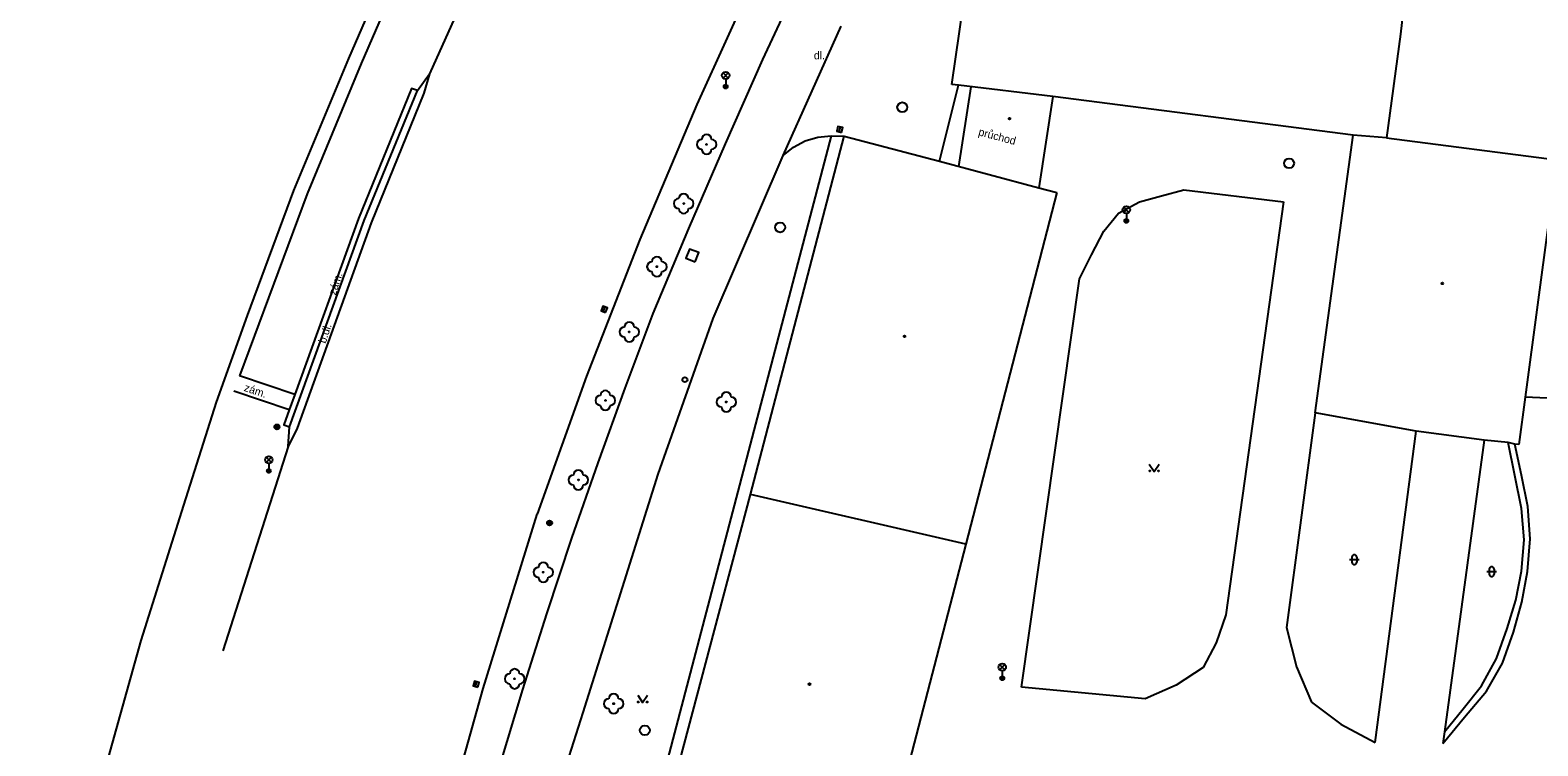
# Model space of a CAD drawing. Extents: x -599770 to -598493, y -1162076 to -1159209.
# Drawn here: x -599183.4 to -599106.9, y -1159771.9 to -1159735.7 of the extents above; entities that cross this region are included whole.
import ezdxf

# ---------------------------------------------------------------- set-up
doc = ezdxf.new("R2010")
doc.units = 0
doc.layers.add('Podklad', color=7, linetype='Continuous')

msp = doc.modelspace()

# ---------------------------------------------------------------- linework, layer by layer
at = {"layer": 'Podklad'}
for p, q in [((-599148.222, -1159738.09), (-599147.957, -1159737.825)), ((-599148.222, -1159737.825), (-599147.957, -1159738.09)), ((-599148.09, -1159738.145), (-599148.09, -1159738.52)), ((-599142.342, -1159740.811), (-599142.278, -1159740.569)), ((-599127.913, -1159744.9), (-599127.648, -1159744.635)), ((-599127.913, -1159744.635), (-599127.648, -1159744.9)), ((-599127.78, -1159744.955), (-599127.78, -1159745.33)), ((-599154.293, -1159749.927), (-599154.207, -1159749.693)), ((-599171.383, -1159757.57), (-599171.118, -1159757.305)), ((-599171.383, -1159757.305), (-599171.118, -1159757.57)), ((-599171.25, -1159757.625), (-599171.25, -1159758)), ((-599116.473, -1159762.498), (-599115.973, -1159762.498)), ((-599116.348, -1159762.373), (-599116.348, -1159762.623)), ((-599116.098, -1159762.373), (-599116.098, -1159762.623)), ((-599109.513, -1159763.108), (-599109.013, -1159763.108)), ((-599109.388, -1159762.983), (-599109.388, -1159763.233)), ((-599109.138, -1159762.983), (-599109.138, -1159763.233)), ((-599134.203, -1159768.08), (-599133.938, -1159767.815)), ((-599134.203, -1159767.815), (-599133.938, -1159768.08)), ((-599160.773, -1159768.931), (-599160.707, -1159768.689)), ((-599134.07, -1159768.135), (-599134.07, -1159768.51))]:
    msp.add_line(p, q, dxfattribs=at)
for points in [[(-599153.26, -1159707.54), (-599161.09, -1159723.46), (-599163.45, -1159728.54), (-599165.36, -1159732.81), (-599167.21, -1159737.09), (-599170, -1159743.79)], [(-599152.46, -1159707.57), (-599154.76, -1159712.01), (-599158.88, -1159720.38), (-599160.49, -1159723.74), (-599162.81, -1159728.83), (-599164.72, -1159733.09), (-599166.57, -1159737.36), (-599169.31, -1159743.95)], [(-599136.92, -1159717.88), (-599138.17, -1159720.27), (-599140.25, -1159724.46), (-599142.28, -1159728.67), (-599143.65, -1159731.64), (-599146.22, -1159737.15), (-599148.12, -1159741.43), (-599149.97, -1159745.72), (-599151.78, -1159750.03)], [(-599157.51, -1159725.43), (-599163.1, -1159737.88)], [(-599146.48, -1159732.66), (-599149.55, -1159739.43), (-599152.44, -1159746.27), (-599155.14, -1159753.2), (-599157.65, -1159760.19)], [(-599113.55, -1159732.91), (-599113.89, -1159735.87)], [(-599136.62, -1159738.41), (-599136.05, -1159734.45)], [(-599145.18, -1159742.01), (-599142.237, -1159735.454)], [(-599113.89, -1159735.87), (-599114.59, -1159741.12)], [(-599163.1, -1159737.88), (-599163.4, -1159738.85), (-599166.06, -1159745.42), (-599169.82, -1159755.84), (-599170.27, -1159756.76)], [(-599163.72, -1159738.72), (-599163.1, -1159737.88)], [(-599170.21, -1159755.76), (-599166.42, -1159745.31), (-599163.72, -1159738.72)], [(-599163.72, -1159738.72), (-599164.01, -1159738.62), (-599166.7, -1159745.2), (-599169.94, -1159754.13)], [(-599137.26, -1159742.31), (-599136.29, -1159738.45)], [(-599136.29, -1159738.45), (-599136.62, -1159738.41)], [(-599131.5, -1159739.03), (-599136.29, -1159738.45)], [(-599135.658, -1159738.527), (-599135.66, -1159738.54), (-599136.29, -1159742.567)], [(-599131.5, -1159739.03), (-599132.22, -1159743.65)], [(-599116.29, -1159740.99), (-599131.5, -1159739.03)], [(-599142.75, -1159741.01), (-599152.2, -1159777.08), (-599155.73, -1159776.65)], [(-599146.84, -1159759.19), (-599142.09, -1159741.03)], [(-599145.18, -1159742.01), (-599144.65, -1159741.59), (-599144.06, -1159741.28), (-599143.42, -1159741.08), (-599142.75, -1159741.01)], [(-599142.75, -1159741.01), (-599142.09, -1159741.03)], [(-599142.09, -1159741.03), (-599137.26, -1159742.31)], [(-599118.21, -1159755.06), (-599116.29, -1159740.99)], [(-599114.59, -1159741.12), (-599116.29, -1159740.99)], [(-599114.59, -1159741.12), (-599105.96, -1159742.23)], [(-599148.73, -1159750.28), (-599145.18, -1159742.01)], [(-599137.26, -1159742.31), (-599132.22, -1159743.65)], [(-599170, -1159743.79), (-599172.35, -1159750.12), (-599173.92, -1159754.52), (-599175.57, -1159759.74), (-599177.74, -1159766.59), (-599183.35, -1159786.68)], [(-599169.31, -1159743.95), (-599172.74, -1159753.19)], [(-599131.31, -1159743.89), (-599135.91, -1159761.72)], [(-599132.22, -1159743.65), (-599131.31, -1159743.89)], [(-599127.11, -1159744.37), (-599125.99, -1159744.06)], [(-599125.99, -1159744.06), (-599124.87, -1159743.76)], [(-599124.87, -1159743.76), (-599119.81, -1159744.36)], [(-599128.93, -1159745.85), (-599128.17, -1159744.93)], [(-599128.17, -1159744.93), (-599127.11, -1159744.37)], [(-599119.81, -1159744.36), (-599122.73, -1159765.3)], [(-599106.34, -1159745.16), (-599107.56, -1159754.26)], [(-599129.54, -1159747.05), (-599128.93, -1159745.85)], [(-599130.16, -1159748.26), (-599129.54, -1159747.05)], [(-599133.09, -1159768.97), (-599130.16, -1159748.26)], [(-599151.78, -1159750.03), (-599153.2, -1159753.81), (-599154.58, -1159757.6), (-599155.9, -1159761.41), (-599157.17, -1159765.24), (-599158.39, -1159769.09), (-599159.55, -1159772.95), (-599160.67, -1159776.83), (-599161.73, -1159780.72)], [(-599151.51, -1159758.16), (-599148.73, -1159750.28)], [(-599169.94, -1159754.13), (-599172.74, -1159753.19)], [(-599170.22, -1159754.9), (-599173.02, -1159753.96)], [(-599169.94, -1159754.13), (-599170.22, -1159754.9)], [(-599170.22, -1159754.9), (-599170.49, -1159755.66), (-599170.21, -1159755.76)], [(-599107.56, -1159754.26), (-599107.88, -1159756.67)], [(-599102.37, -1159754.5), (-599107.56, -1159754.26)], [(-599118.21, -1159755.06), (-599119.67, -1159765.94)], [(-599113.08, -1159755.99), (-599118.21, -1159755.06)], [(-599170.27, -1159756.76), (-599170.21, -1159755.76)], [(-599115.16, -1159771.76), (-599113.08, -1159755.99)], [(-599109.64, -1159756.45), (-599113.08, -1159755.99)], [(-599109.64, -1159756.45), (-599111.65, -1159771.23)], [(-599108.43, -1159756.56), (-599109.64, -1159756.45)], [(-599170.27, -1159756.76), (-599173.59, -1159767.13)], [(-599108.08, -1159756.64), (-599108.43, -1159756.56)], [(-599108.09, -1159758.23), (-599108.43, -1159756.56)], [(-599107.88, -1159756.67), (-599108.08, -1159756.64)], [(-599107.75, -1159758.22), (-599108.08, -1159756.64)], [(-599126.62, -1159757.655), (-599126.37, -1159758.03), (-599126.12, -1159757.655)], [(-599155.32, -1159770.24), (-599151.51, -1159758.16)], [(-599107.75, -1159759.91), (-599108.09, -1159758.23)], [(-599107.43, -1159759.81), (-599107.75, -1159758.22)], [(-599151.8, -1159777.91), (-599146.84, -1159759.19)], [(-599135.91, -1159761.72), (-599146.84, -1159759.19)], [(-599160.39, -1159769.03), (-599157.65, -1159760.19)], [(-599107.62, -1159761.49), (-599107.75, -1159759.91)], [(-599107.31, -1159761.45), (-599107.43, -1159759.81)], [(-599135.91, -1159761.72), (-599140.59, -1159779.75)], [(-599107.75, -1159763.08), (-599107.62, -1159761.49)], [(-599107.45, -1159763.1), (-599107.31, -1159761.45)], [(-599108.04, -1159764.55), (-599107.75, -1159763.08)], [(-599107.73, -1159764.65), (-599107.45, -1159763.1)], [(-599108.48, -1159765.99), (-599108.04, -1159764.55)], [(-599108.16, -1159766.17), (-599107.73, -1159764.65)], [(-599122.73, -1159765.3), (-599123.22, -1159766.71)], [(-599119.67, -1159765.94), (-599119.16, -1159767.93)], [(-599109.01, -1159767.51), (-599108.48, -1159765.99)], [(-599108.71, -1159767.74), (-599108.16, -1159766.17)], [(-599123.22, -1159766.71), (-599123.88, -1159767.97)], [(-599109.78, -1159768.89), (-599109.01, -1159767.51)], [(-599109.53, -1159769.16), (-599108.71, -1159767.74)], [(-599123.88, -1159767.97), (-599125.25, -1159768.86)], [(-599119.16, -1159767.93), (-599118.39, -1159769.72)], [(-599165.83, -1159788.5), (-599160.39, -1159769.03)], [(-599152.55, -1159769.365), (-599152.3, -1159769.74), (-599152.05, -1159769.365)], [(-599126.82, -1159769.56), (-599133.09, -1159768.97)], [(-599125.25, -1159768.86), (-599126.82, -1159769.56)], [(-599110.71, -1159770.06), (-599109.78, -1159768.89)], [(-599110.63, -1159770.49), (-599109.53, -1159769.16)], [(-599118.39, -1159769.72), (-599116.9, -1159770.84)], [(-599111.65, -1159771.23), (-599110.71, -1159770.06)], [(-599158.03, -1159778.8), (-599155.32, -1159770.24)], [(-599116.9, -1159770.84), (-599115.16, -1159771.76)], [(-599111.73, -1159771.82), (-599110.63, -1159770.49)], [(-599111.65, -1159771.23), (-599111.73, -1159771.82)]]:
    msp.add_lwpolyline(points, dxfattribs=at)
for points in [[(-599142.221, -1159740.843), (-599142.157, -1159740.601), (-599142.399, -1159740.537), (-599142.463, -1159740.779)], [(-599149.636, -1159747.403), (-599149.457, -1159746.936), (-599149.924, -1159746.757), (-599150.103, -1159747.224)], [(-599154.176, -1159749.97), (-599154.09, -1159749.736), (-599154.324, -1159749.65), (-599154.41, -1159749.884)], [(-599160.652, -1159768.964), (-599160.586, -1159768.722), (-599160.828, -1159768.656), (-599160.894, -1159768.898)]]:
    msp.add_lwpolyline(points, close=True, dxfattribs=at)
for centre, radius in [((-599148.09, -1159737.957), 0.188), ((-599148.09, -1159738.52), 0.1), ((-599148.09, -1159738.52), 0.0723), ((-599148.09, -1159738.52), 0.0438), ((-599139.14, -1159739.57), 0.25), ((-599133.7, -1159740.15), 0.045), ((-599133.7, -1159740.15), 0.0199), ((-599149.06, -1159741.45), 0.025), ((-599119.53, -1159742.41), 0.25), ((-599150.22, -1159744.45), 0.025), ((-599127.78, -1159744.767), 0.188), ((-599145.33, -1159745.66), 0.25), ((-599127.78, -1159745.33), 0.1), ((-599127.78, -1159745.33), 0.0723), ((-599127.78, -1159745.33), 0.0438), ((-599151.58, -1159747.65), 0.025), ((-599111.76, -1159748.5), 0.045), ((-599111.76, -1159748.5), 0.0199), ((-599152.98, -1159750.96), 0.025), ((-599139.02, -1159751.18), 0.045), ((-599139.02, -1159751.18), 0.0199), ((-599150.16, -1159753.38), 0.125), ((-599154.19, -1159754.43), 0.025), ((-599148.06, -1159754.51), 0.025), ((-599170.84, -1159755.77), 0.125), ((-599170.84, -1159755.77), 0.1), ((-599170.84, -1159755.77), 0.075), ((-599170.84, -1159755.77), 0.05), ((-599170.84, -1159755.77), 0.025), ((-599171.25, -1159757.438), 0.188), ((-599171.25, -1159758), 0.1), ((-599171.25, -1159758), 0.0723), ((-599171.25, -1159758), 0.0438), ((-599126.595, -1159758.005), 0.025), ((-599126.145, -1159758.005), 0.025), ((-599155.56, -1159758.46), 0.025), ((-599157.02, -1159760.64), 0.125), ((-599157.02, -1159760.64), 0.1), ((-599157.02, -1159760.64), 0.075), ((-599157.02, -1159760.64), 0.05), ((-599157.02, -1159760.64), 0.025), ((-599157.34, -1159763.14), 0.025), ((-599134.07, -1159767.948), 0.188), ((-599158.79, -1159768.54), 0.025), ((-599134.07, -1159768.51), 0.1), ((-599134.07, -1159768.51), 0.0723), ((-599134.07, -1159768.51), 0.0438), ((-599143.84, -1159768.81), 0.045), ((-599143.84, -1159768.81), 0.0199), ((-599153.77, -1159769.8), 0.025), ((-599152.525, -1159769.715), 0.025), ((-599152.075, -1159769.715), 0.025), ((-599152.19, -1159771.15), 0.25)]:
    msp.add_circle(centre, radius, dxfattribs=at)
for centre, radius, start, end in [((-599149.06, -1159741.2), 0.25, 0, 180), ((-599149.31, -1159741.45), 0.25, 90, 270), ((-599149.06, -1159741.7), 0.25, 180, 0), ((-599148.81, -1159741.45), 0.25, 270, 90), ((-599150.47, -1159744.45), 0.25, 90, 270), ((-599150.22, -1159744.2), 0.25, 0, 180), ((-599149.97, -1159744.45), 0.25, 270, 90), ((-599150.22, -1159744.7), 0.25, 180, 0), ((-599151.58, -1159747.4), 0.25, 0, 180), ((-599151.83, -1159747.65), 0.25, 90, 270), ((-599151.58, -1159747.9), 0.25, 180, 0), ((-599151.33, -1159747.65), 0.25, 270, 90), ((-599153.23, -1159750.96), 0.25, 90, 270), ((-599152.98, -1159750.71), 0.25, 0, 180), ((-599152.73, -1159750.96), 0.25, 270, 90), ((-599152.98, -1159751.21), 0.25, 180, 0), ((-599154.19, -1159754.18), 0.25, 0, 180), ((-599148.06, -1159754.26), 0.25, 0, 180), ((-599154.44, -1159754.43), 0.25, 90, 270), ((-599154.19, -1159754.68), 0.25, 180, 0), ((-599153.94, -1159754.43), 0.25, 270, 90), ((-599148.31, -1159754.51), 0.25, 90, 270), ((-599148.06, -1159754.76), 0.25, 180, 0), ((-599147.81, -1159754.51), 0.25, 270, 90), ((-599155.56, -1159758.21), 0.25, 0, 180), ((-599155.81, -1159758.46), 0.25, 90, 270), ((-599155.56, -1159758.71), 0.25, 180, 0), ((-599155.31, -1159758.46), 0.25, 270, 90), ((-599116.223, -1159762.373), 0.125, 0, 180), ((-599157.59, -1159763.14), 0.25, 90, 270), ((-599157.34, -1159762.89), 0.25, 0, 180), ((-599157.09, -1159763.14), 0.25, 270, 90), ((-599116.223, -1159762.623), 0.125, 180, 0), ((-599109.263, -1159762.983), 0.125, 0, 180), ((-599109.263, -1159763.233), 0.125, 180, 0), ((-599157.34, -1159763.39), 0.25, 180, 0), ((-599159.04, -1159768.54), 0.25, 90, 270), ((-599158.79, -1159768.29), 0.25, 0, 180), ((-599158.54, -1159768.54), 0.25, 270, 90), ((-599158.79, -1159768.79), 0.25, 180, 0), ((-599153.77, -1159769.55), 0.25, 0, 180), ((-599154.02, -1159769.8), 0.25, 90, 270), ((-599153.77, -1159770.05), 0.25, 180, 0), ((-599153.52, -1159769.8), 0.25, 270, 90)]:
    msp.add_arc(centre, radius, start, end, dxfattribs=at)

# ---------------------------------------------------------------- texts
msp.add_text('dl.', height=0.4, dxfattribs=at).set_placement((-599143.62, -1159737.14))
for s, rotation, p in [('průchod', 345.14, (-599135.31, -1159740.99)), ('zám.', 71.87, (-599167.86, -1159749.12)), ('b.dl.', 72.03, (-599168.37, -1159751.57)), ('zám.', 341.55, (-599172.54, -1159753.94))]:
    msp.add_text(s, height=0.4, rotation=rotation, dxfattribs=at).set_placement(p)

doc.saveas('drawing.dxf')
